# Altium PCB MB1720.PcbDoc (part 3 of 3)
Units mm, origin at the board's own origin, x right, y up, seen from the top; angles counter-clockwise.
Board outline 62.4 x 34.09 mm, 4 copper layers (Top Layer, MidLayer 1, MidLayer 2, Bottom Layer), stack 1.594 mm thick; 82 components, 66 nets, 241 pads, 1258 vias.
Unrouted connection lines stored in the file: 1.
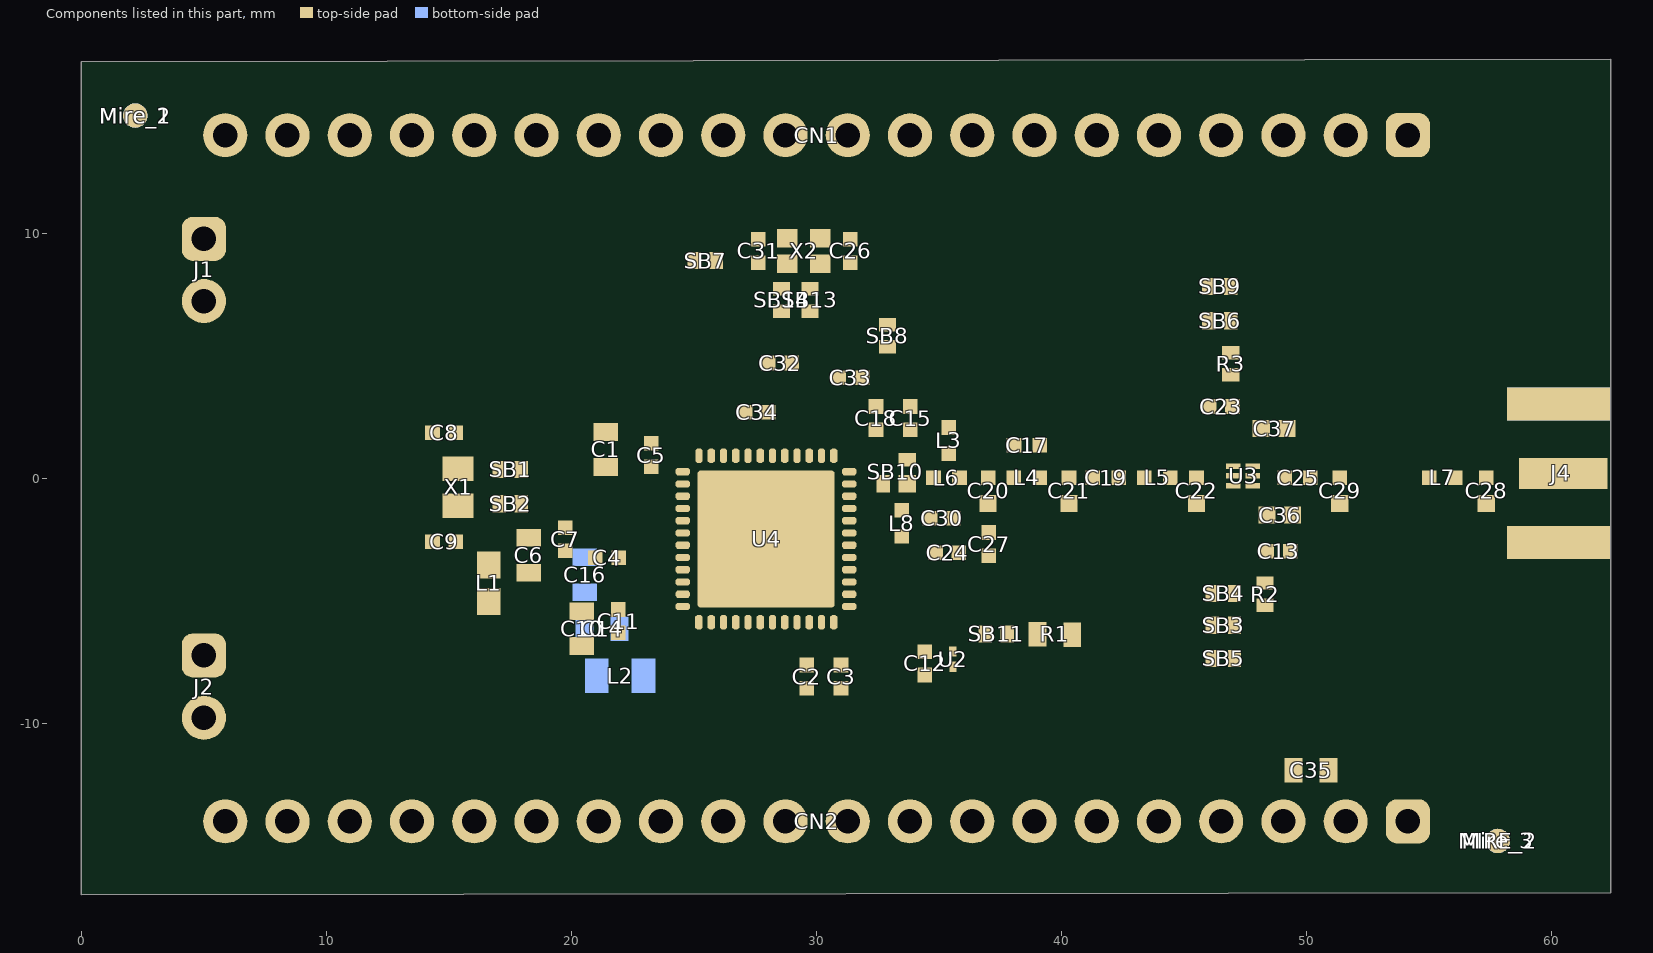
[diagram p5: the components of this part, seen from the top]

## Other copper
Top Layer:
  pour cut-out: 34.356,-0.946 cw(c35.071,-0.741) 34.335,-0.632 ccw(c34.401,-0.785)
  pour cut-out: 32.249,-2.012 32.249,-2.397 ccw(c33.845,-2.397) 32.716,-3.526 33.479,-4.288 33.479,-4.454 32.175,-3.14 32.184,-2.011
  pour cut-out: 17.174,-2.061 ccw(c16.199,-4.435) 16.103,-1.871 cw(c16.605,-2.154)
  pour cut-out: 16.715,0.48 ccw(c15.159,-1.56) 15.729,0.941 cw(c16.141,0.538)
  pour cut-out: 34.178,0.962 34.933,0.962 34.933,0.424 34.176,0.424
  pour cut-out: 32.365,-0.689 32.905,-0.689 32.905,-1.094 32.392,-1.094
  pour cut-out: 32.686,0.561 33.222,0.561 33.222,0.169 32.694,0.169
  pour cut-out: 38.501,1.845 38.675,1.845 38.675,-0.48 38.508,-0.48
  pour cut-out: 35.218,-0.481 35.378,-0.481 35.378,0.196 35.218,0.196
  pour cut-out: 48.6,-0.475 48.6,-0.126 48.329,-0.126 48.329,-0.473
  pour cut-out: 48.62,0.529 48.341,0.529 48.341,0.345 48.62,0.345
  pour cut-out: 43.82,0.53 43.98,0.53 43.98,-0.47 43.82,-0.47
  pour cut-out: 32.981,8.794 27.995,8.794 26.793,9.996 26.793,11.656 32.981,11.656 32.981,13.086 24.102,13.141 24.102,7.638 27.291,5.311 27.291,6.46 32.651,6.46 32.651,5.233 33.793,5.233 37.223,8.23 37.223,13.086 32.981,13.086
  pour cut-out: 18.899,-2.146 18.899,-2.63 19.377,-2.63 19.377,-2.535 20.626,-2.535 20.629,-2.897 21.33,-2.897 21.33,-2.154
  text "Layer" at 1.328,147.624 h1.52
  text "Name" at 11.74,147.624 h1.52
  text "Material" at 35.355,147.624 h1.52
  text "Thickness" at 57.193,147.624 h1.52
  text "Constant" at 73.699,147.624 h1.52
  text "Board Layer Stack" at 88.173,147.624 h1.52
  text "Top Overlay" at 11.74,144.576 h1.52
  text "Top Solder" at 11.74,141.528 h1.52
  text "Solder Resist" at 35.355,141.528 h1.52
  text "0.79mil" at 57.193,141.528 h1.52
  text "3.5" at 73.699,141.528 h1.52
  text "1" at 1.328,138.48 h1.52
  text "Top Layer" at 11.74,138.48 h1.52
  text "2.13mil" at 57.193,138.48 h1.52
  text "Dielectric 1" at 11.74,135.432 h1.52
  text "1 X 2116" at 35.355,135.432 h1.52
  text "4.25mil" at 57.193,135.432 h1.52
  text "3.6" at 73.699,135.432 h1.52
  text "2" at 1.328,132.384 h1.52
  text "MidLayer 1" at 11.74,132.384 h1.52
  text "1.38mil" at 57.193,132.384 h1.52
  text "Dielectric 2" at 11.74,129.336 h1.52
  text "FR4 TG135" at 35.355,129.336 h1.52
  text "47.24mil" at 57.193,129.336 h1.52
  text "4.7" at 73.699,129.336 h1.52
  text "3" at 1.328,126.288 h1.52
  text "MidLayer 2" at 11.74,126.288 h1.52
  text "1.38mil" at 57.193,126.288 h1.52
  text "Dielectric 3" at 11.74,123.24 h1.52
  text "1 X 2116" at 35.355,123.24 h1.52
  text "4.25mil" at 57.193,123.24 h1.52
  text "3.6" at 73.699,123.24 h1.52
  text "4" at 1.328,120.192 h1.52
  text "Bottom Layer" at 11.74,120.192 h1.52
  text "2.13mil" at 57.193,120.192 h1.52
  text "Bottom Solder" at 11.74,117.144 h1.52
  text "Solder Resist" at 35.355,117.144 h1.52
  text "0.79mil" at 57.193,117.144 h1.52
  text "3.5" at 73.699,117.144 h1.52
  text "Bottom Overlay" at 11.74,114.096 h1.52
MidLayer 1:
  pour cut-out: 28.352,4.426 26.26,4.426 ccw(c26.26,4.22) 26.054,4.22 26.054,3.41 26.511,2.953 27.996,2.953 ccw(c27.996,3.331) 28.263,3.063 28.459,3.26 ccw(c28.323,3.396) 28.516,3.396 28.516,4.262 ccw(c28.352,4.262)
  pour cut-out: 29.391,6.735 27.347,6.735 ccw(c27.347,6.547) 27.158,6.547 27.158,5.251 27.569,4.84 29.335,4.84 ccw(c29.335,5.055) 29.551,5.055 29.551,6.575 ccw(c29.391,6.575)
  pour cut-out: 27.246,9.716 26.244,9.716 26.244,7.977 27.059,7.977 27.559,8.477 27.559,9.403
  pour cut-out: 34.76,10.098 32.569,10.098 32.569,8.961 30.364,6.736 30.364,3.066 32.447,3.066 34.76,6.536
  pour cut-out: 15.008,-6.607 16.887,-6.607 16.887,-4.792 14.987,-4.792
  pour cut-out: 48.694,0.862 51.479,0.862 53.194,0.862 59.15,0.862 59.15,-0.85 48.684,-0.85
  pour cut-out: 35.034,0.815 37.357,0.815 37.357,1.893 39.885,1.893 39.885,0.865 46.007,0.865 46.007,-0.903 35.578,-0.929 35.026,-0.377
MidLayer 2:
  pour cut-out: 25.169,-3.911 25.169,-5.203 26.177,-5.203
  pour cut-out: 25.16,-1.129 25.16,0.162 26.168,0.162
  pour cut-out: 25.498,0.166 25.13,0.166 25.13,-5.217 25.498,-5.217
  pour cut-out: 30.628,0.161 30.996,0.161 30.996,-5.222 30.628,-5.222
  pour cut-out: 30.966,-1.134 30.966,0.157 29.958,0.157
Bottom Layer:
  pour cut-out: 32.038,10.963 28.254,10.963 27.087,9.796 27.087,6.33 32.967,6.33 33.344,6.707 33.344,9.657

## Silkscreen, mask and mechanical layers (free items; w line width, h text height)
Top Overlay:
  drawing of 185 lines, arcs and shapes, not listed
  text "UART_RX" at 2.2,11.55 h1.5 r270
  text "CLK" at 0.3,1.3 h1.5 r270
  text "UART_TX" at 2.25,-5.6 h1.5 r270
  text "MB1720" at 10.67,-10.041 h1.5 r90
Bottom Overlay:
  text "C" at 18.5,-8.8 h10
  text "MB1720_M4" at 19.75,-11.45 h2.5
Top Paste:
  lines w0.5: 12.622,-7.963 12.622,-9.862 16.82,-9.862 ; 12.629,-7.963 12.629,11.36 16.537,11.36 ; 16.537,11.346 53.232,11.346 53.232,1.286 ; 26.961,-9.859 32.942,-9.852 ; 27.895,-9.862 28.96,-9.862 ; 34.597,-9.856 40.164,-9.847 ; 42.939,-9.864 45.273,-9.847 ; 48.19,-9.862 53.224,-9.862 ; 53.224,-9.876 53.224,-1.391
Top Solder:
  lines w1.5: 16.451,-9.862 12.622,-9.862 12.629,11.36 17.197,11.359 ; 16.984,11.359 53.229,11.359 53.229,1.467 ; 27.292,-9.862 32.663,-9.862 ; 35.046,-9.856 39.783,-9.858 ; 43.325,-9.858 44.875,-9.858 ; 47.304,-9.862 53.228,-9.862 ; 53.228,-9.873 53.228,-1.478
  lines w2: 12.908,-8.547 13.872,-9.511 ; 12.926,10.11 13.89,11.074 ; 51.888,11.096 52.852,10.132 ; 52.191,-9.531 52.973,-8.415
M1-Board Shape:
  the board outline again, w0.3
Drill Drawing:
  lines w0.254: 0.826,95.171 1.249,95.171 1.672,94.748 2.096,95.171 2.519,95.171 2.096,95.595 2.519,96.018 2.096,96.018 1.672,96.441 1.249,96.018 0.826,96.018 1.249,95.595 0.826,95.171 ; 0.826,98.558 2.519,98.558 2.519,100.251 0.826,100.251 0.826,98.558
  lines w0.381: -0.693,93.605 323.27,93.605 ; -0.693,101.225 323.27,101.225 ; 13.299,89.795 13.299,105.035 ; 28.535,89.795 28.535,105.035 ; 56.213,89.795 56.213,105.035 ; 69.063,89.795 69.063,105.035 ; 87.701,89.795 87.701,105.035 ; 125.79,89.795 125.79,105.035 ; 140.772,89.795 140.772,105.035 ; 159.715,89.795 159.715,105.035 ; 176.221,89.795 176.221,105.035 ; 197.906,89.795 197.906,105.035 ; 231.78,89.795 231.78,105.035 ; 265.654,89.795 265.654,105.035 ; 287.644,89.795 287.644,105.035 ; -0.693,89.795 323.27,89.795 323.27,105.035 -0.693,105.035 -0.693,89.795
  text "Symbol" at 1.593,102.368 h1.83
  text "Count" at 14.442,102.368 h1.83
  text "Hole Size" at 29.678,102.368 h1.83
  text "Plated" at 57.356,102.368 h1.83
  text "Hole Type" at 70.206,102.368 h1.83
  text "Drill Layer Pair" at 88.844,102.368 h1.83
  text "Via/Pad" at 126.933,102.368 h1.83
  text "Pad Shape" at 141.915,102.368 h1.83
  text "Template" at 160.858,102.368 h1.83
  text "Description" at 177.364,102.368 h1.83
  text "Hole Tolerance (+)" at 199.049,102.368 h1.83
  text "Hole Tolerance (-)" at 232.923,102.368 h1.83
  text "Hole Length" at 266.797,102.368 h1.83
  text "Routed Path Length" at 288.787,102.368 h1.83
  text "44" at 14.442,98.558 h1.52
  text "1.000mm (39.37mil)" at 29.678,98.558 h1.52
  text "PTH" at 57.356,98.558 h1.52
  text "Round" at 70.206,98.558 h1.52
  text "Top Layer - Bottom Layer" at 88.844,98.558 h1.52
  text "Pad" at 126.933,98.558 h1.52
  text "(Mixed)" at 141.915,98.558 h1.52
  text "(Mixed)" at 160.858,98.558 h1.52
  text "-" at 266.797,98.558 h1.52
  text "-" at 288.787,98.558 h1.52
  text "922" at 14.442,94.748 h1.52
  text "0.200mm (7.87mil)" at 29.678,94.748 h1.52
  text "PTH" at 57.356,94.748 h1.52
  text "Round" at 70.206,94.748 h1.52
  text "Top Layer - Bottom Layer" at 88.844,94.748 h1.52
  text "Via" at 126.933,94.748 h1.52
  text "Rounded" at 141.915,94.748 h1.52
  text "(Mixed)" at 160.858,94.748 h1.52
  text "-" at 266.797,94.748 h1.52
  text "-" at 288.787,94.748 h1.52
  text "966 Total" at 14.442,90.938 h1.52
  text "mils" at 23.641,75.946 h2.54
  text "mils" at 34.695,75.946 h2.54

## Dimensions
62.401,-16.907 to 0.031,-16.969 on M3-Top Dimensions
0,16.953 to 0.031,-16.969 on M3-Top Dimensions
